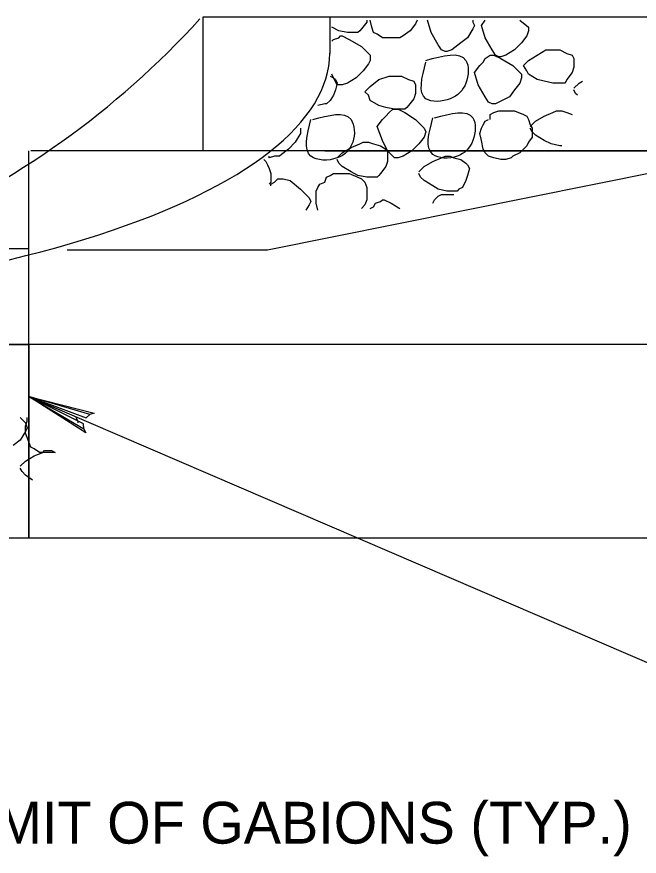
# Model space of a CAD drawing. Extents: x 593 to 1473, y 721 to 1315.
# Drawn here: x 853.8 to 898.5, y 813.2 to 873.4 of the extents above; entities that cross this region are included whole.
import ezdxf

# ---------------------------------------------------------------- set-up
doc = ezdxf.new("R2010")
doc.units = 0
doc.layers.add('1', color=7, linetype='Continuous')
doc.layers.add('2', color=7, linetype='Continuous')

msp = doc.modelspace()

# ---------------------------------------------------------------- linework, layer by layer
at = {"layer": '1'}
msp.add_lwpolyline([(858.655, 843.824), (858.63, 844.193), (854.709, 846.141), (858.655, 843.824), (858.79, 843.549), (854.709, 846.141), (858.807, 844.615), (859.082, 844.85), (854.709, 846.141), (859.394, 844.953), (859.082, 844.85)], dxfattribs=at)
msp.add_lwpolyline([(858.655, 843.824), (858.63, 844.193), (854.709, 846.141), (858.655, 843.824), (858.79, 843.549), (854.709, 846.141), (858.807, 844.615), (859.082, 844.85), (854.709, 846.141), (859.394, 844.953), (859.082, 844.85)], dxfattribs=at)
at = {"layer": '2'}
for p, q in [((876.334, 870.766), (876.334, 873.391)), ((932.209, 868.766), (871.834, 856.641)), ((861.959, 863.766), (854.834, 863.766)), ((871.459, 863.766), (861.959, 863.766)), ((872.584, 863.766), (871.459, 863.766)), ((876.334, 863.766), (872.584, 863.766)), ((819.834, 856.766), (854.709, 856.766)), ((871.834, 856.641), (857.459, 856.641)), ((854.709, 846.141), (925.949, 815.516)), ((854.709, 846.141), (925.949, 815.516))]:
    msp.add_line(p, q, dxfattribs=at)
for points in [[(867.209, 863.766), (867.209, 873.391), (876.084, 873.391)], [(876.084, 873.391), (932.209, 873.391), (932.209, 863.766), (871.459, 863.766)], [(876.959, 872.391), (876.459, 872.641)], [(876.459, 872.641), (876.459, 872.641)], [(878.959, 873.016), (878.584, 872.516)], [(878.959, 873.141), (878.959, 873.016)], [(879.334, 872.641), (879.209, 873.141)], [(879.459, 872.266), (879.334, 872.641)], [(882.459, 872.891), (882.084, 872.391)], [(882.584, 873.141), (882.459, 872.891)], [(883.584, 872.266), (883.334, 873.141)], [(886.584, 873.141), (886.584, 873.016)], [(886.584, 873.016), (886.709, 872.766)], [(886.709, 872.766), (886.584, 872.516)], [(887.209, 872.766), (887.459, 873.141)], [(887.459, 871.891), (887.209, 872.766)], [(889.959, 873.141), (890.584, 872.641)], [(890.584, 872.641), (890.584, 872.391)], [(877.584, 872.266), (876.959, 872.391)], [(876.959, 871.891), (877.084, 872.016)], [(877.084, 872.016), (877.209, 872.016)], [(877.209, 872.016), (877.709, 871.766)], [(878.334, 872.266), (877.584, 872.266)], [(878.459, 872.391), (878.334, 872.266)], [(878.584, 872.516), (878.459, 872.391)], [(879.709, 872.141), (879.459, 872.266)], [(880.084, 871.891), (879.709, 872.141)], [(881.584, 872.016), (881.334, 871.891)], [(882.084, 872.391), (881.584, 872.016)], [(884.084, 871.391), (883.584, 872.266)], [(886.584, 872.516), (886.209, 871.891)], [(890.459, 872.016), (890.084, 871.516)], [(890.584, 872.391), (890.459, 872.016)], [(876.459, 871.641), (876.584, 871.766)], [(876.584, 871.766), (876.959, 871.891)], [(877.709, 871.766), (878.584, 871.266)], [(880.584, 871.891), (880.084, 871.891)], [(880.959, 871.891), (880.584, 871.891)], [(881.334, 871.891), (880.959, 871.891)], [(885.709, 871.516), (885.084, 871.016)], [(886.209, 871.891), (885.709, 871.516)], [(887.959, 871.016), (887.459, 871.891)], [(890.084, 871.516), (889.584, 871.016)], [(878.584, 871.266), (879.209, 870.641)], [(884.334, 871.016), (884.084, 871.391)], [(884.584, 870.891), (884.334, 871.016)], [(884.709, 870.891), (884.584, 870.891)], [(885.084, 871.016), (884.709, 870.891)], [(888.209, 870.641), (887.959, 871.016)], [(889.584, 871.016), (888.959, 870.641)], [(891.209, 870.641), (891.834, 871.016)], [(891.834, 871.016), (892.084, 871.016)], [(892.084, 871.016), (892.459, 871.016)], [(892.459, 871.016), (892.834, 871.016)], [(892.834, 871.016), (893.334, 870.766)], [(879.209, 870.266), (879.084, 870.016)], [(879.209, 870.641), (879.209, 870.266)], [(887.334, 870.141), (887.459, 870.391)], [(887.459, 870.391), (887.834, 870.641)], [(887.834, 870.641), (887.959, 870.641)], [(887.959, 870.641), (888.084, 870.641)], [(888.084, 870.641), (888.584, 870.391)], [(888.459, 870.516), (888.209, 870.641)], [(888.584, 870.516), (888.459, 870.516)], [(888.959, 870.641), (888.584, 870.516)], [(888.584, 870.391), (889.459, 869.891)], [(890.209, 869.891), (890.584, 870.266)], [(890.584, 870.266), (891.209, 870.641)], [(893.334, 870.766), (893.709, 870.641)], [(893.709, 870.641), (893.834, 870.391)], [(893.834, 870.391), (893.834, 870.141)], [(879.084, 870.016), (878.709, 869.516)], [(886.709, 869.391), (887.084, 869.891)], [(887.084, 869.891), (887.334, 870.141)], [(889.459, 869.891), (890.084, 869.266)], [(890.459, 869.516), (890.209, 869.891)], [(893.834, 869.766), (893.709, 869.391)], [(893.834, 870.141), (893.834, 869.766)], [(876.334, 869.141), (876.584, 869.016)], [(876.584, 869.016), (876.459, 869.266)], [(876.834, 868.516), (876.584, 869.016)], [(876.584, 869.016), (876.709, 868.891)], [(878.209, 869.016), (877.584, 868.641)], [(878.709, 869.516), (878.209, 869.016)], [(879.834, 868.891), (880.584, 869.141)], [(880.584, 869.141), (880.709, 869.141)], [(880.709, 869.141), (881.209, 869.141)], [(881.209, 869.141), (881.459, 869.141)], [(881.459, 869.141), (881.959, 868.891)], [(886.959, 868.516), (886.709, 869.391)], [(890.084, 869.016), (889.959, 868.641)], [(890.084, 869.266), (890.084, 869.016)], [(890.584, 869.266), (890.459, 869.516)], [(891.209, 868.891), (890.584, 869.266)], [(893.709, 869.391), (893.334, 868.891)], [(876.709, 868.891), (876.834, 868.641)], [(876.834, 868.641), (876.709, 868.141)], [(877.084, 868.516), (876.834, 868.516)], [(877.209, 868.516), (877.084, 868.516)], [(877.584, 868.641), (877.209, 868.516)], [(879.209, 868.391), (879.834, 868.891)], [(881.959, 868.891), (882.334, 868.766)], [(882.334, 868.766), (882.459, 868.516)], [(882.459, 868.516), (882.459, 868.391)], [(887.459, 867.641), (886.959, 868.516)], [(889.959, 868.641), (889.584, 868.141)], [(891.709, 868.766), (891.209, 868.891)], [(892.334, 868.641), (891.709, 868.766)], [(893.084, 868.641), (892.334, 868.641)], [(893.209, 868.641), (893.084, 868.641)], [(893.334, 868.891), (893.209, 868.641)], [(893.834, 868.266), (894.209, 868.641)], [(894.209, 868.641), (894.459, 868.766)], [(876.709, 868.141), (876.584, 867.766)], [(878.834, 868.016), (879.209, 868.391)], [(879.084, 867.766), (878.834, 868.016)], [(882.459, 867.891), (882.334, 867.516)], [(882.459, 868.391), (882.459, 867.891)], [(889.584, 868.141), (889.209, 867.641)], [(893.959, 867.891), (893.834, 868.141)], [(894.084, 867.766), (893.959, 867.891)], [(876.334, 867.391), (876.084, 867.141)], [(876.584, 867.766), (876.334, 867.391)], [(879.209, 867.391), (879.084, 867.766)], [(879.834, 867.016), (879.209, 867.391)], [(882.334, 867.516), (881.959, 867.016)], [(887.709, 867.266), (887.459, 867.641)], [(887.959, 867.141), (887.709, 867.266)], [(888.459, 867.266), (888.209, 867.141)], [(889.209, 867.641), (888.459, 867.266)], [(875.959, 867.141), (875.459, 867.016)], [(876.084, 867.141), (875.959, 867.141)], [(880.334, 866.891), (879.834, 867.016)], [(880.959, 866.766), (880.334, 866.891)], [(880.584, 866.516), (880.834, 866.766)], [(880.834, 866.766), (880.959, 866.766)], [(880.959, 866.766), (881.209, 866.766)], [(881.709, 866.766), (880.959, 866.766)], [(881.209, 866.766), (881.709, 866.516)], [(881.834, 866.891), (881.709, 866.766)], [(881.959, 867.016), (881.834, 866.891)], [(888.209, 867.141), (887.959, 867.141)], [(888.084, 866.516), (888.459, 866.641)], [(888.459, 866.641), (889.084, 866.641)], [(889.084, 866.641), (889.584, 866.641)], [(889.584, 866.641), (890.209, 866.391)], [(892.334, 866.516), (892.584, 866.641)], [(892.584, 866.641), (892.959, 866.641)], [(892.959, 866.641), (893.334, 866.516)], [(879.709, 865.516), (880.084, 866.016)], [(880.084, 866.016), (880.334, 866.266)], [(880.334, 866.266), (880.584, 866.516)], [(881.709, 866.516), (882.459, 866.016)], [(882.459, 866.016), (883.084, 865.391)], [(887.459, 865.891), (887.709, 866.016)], [(887.834, 866.391), (888.084, 866.516)], [(887.834, 866.016), (887.834, 866.391)], [(890.209, 866.391), (890.459, 866.266)], [(890.459, 866.266), (890.584, 866.016)], [(890.584, 866.016), (890.709, 865.641)], [(891.084, 865.891), (891.709, 866.266)], [(891.709, 866.266), (892.334, 866.516)], [(893.334, 866.516), (893.709, 866.391)], [(874.209, 865.391), (874.209, 865.266)], [(880.084, 864.516), (879.709, 865.516)], [(883.084, 865.391), (883.209, 865.141)], [(887.084, 865.016), (887.209, 865.391)], [(887.209, 865.391), (887.334, 865.641)], [(887.334, 865.641), (887.459, 865.891)], [(890.709, 865.516), (891.084, 865.891)], [(890.709, 865.641), (890.834, 865.391)], [(890.834, 865.141), (890.709, 865.391)], [(890.834, 865.391), (890.834, 865.141)], [(874.209, 865.016), (873.959, 864.641)], [(874.209, 865.266), (874.209, 865.016)], [(883.209, 865.141), (883.084, 864.766)], [(887.209, 864.516), (887.084, 865.016)], [(890.834, 865.141), (890.834, 864.766)], [(891.084, 864.891), (890.834, 865.141)], [(891.709, 864.516), (891.084, 864.891)], [(873.834, 864.391), (873.334, 863.891)], [(873.959, 864.641), (873.834, 864.391)], [(877.834, 864.016), (878.459, 864.266)], [(878.459, 864.266), (878.709, 864.391)], [(878.709, 864.391), (879.084, 864.391)], [(879.084, 864.391), (879.459, 864.266)], [(879.459, 864.266), (879.959, 864.141)], [(880.459, 863.766), (880.084, 864.516)], [(882.709, 864.266), (882.209, 863.766)], [(883.084, 864.766), (882.709, 864.266)], [(887.334, 863.891), (887.209, 864.516)], [(890.584, 864.391), (890.459, 864.141)], [(890.834, 864.766), (890.584, 864.391)], [(892.209, 864.266), (891.709, 864.516)], [(892.834, 864.141), (892.209, 864.266)], [(875.959, 863.766), (932.209, 863.766), (932.209, 849.891), (854.709, 849.891), (854.709, 856.641)], [(854.709, 856.641), (854.709, 863.766)], [(871.459, 863.766), (867.209, 863.766)], [(873.334, 863.891), (872.834, 863.516)], [(876.834, 863.266), (877.209, 863.641)], [(877.209, 863.641), (877.834, 864.016)], [(879.959, 864.141), (880.334, 863.891)], [(880.334, 863.891), (880.459, 863.766)], [(880.834, 863.391), (880.459, 863.766)], [(880.459, 863.766), (880.459, 863.516)], [(882.209, 863.766), (881.584, 863.391)], [(887.459, 863.641), (887.334, 863.891)], [(887.709, 863.391), (887.459, 863.641)], [(889.959, 863.641), (889.459, 863.391)], [(890.459, 864.141), (889.959, 863.641)], [(892.959, 864.141), (892.834, 864.141)], [(871.584, 863.141), (871.709, 863.016)], [(871.709, 863.016), (871.834, 862.766)], [(872.334, 863.391), (871.959, 863.266)], [(871.959, 863.266), (871.959, 863.391)], [(872.709, 863.391), (872.334, 863.391)], [(872.834, 863.516), (872.709, 863.391)], [(876.959, 862.891), (876.834, 863.141)], [(880.459, 863.016), (880.334, 862.641)], [(880.459, 863.516), (880.459, 863.016)], [(880.959, 863.266), (880.834, 863.391)], [(881.209, 863.266), (880.959, 863.266)], [(881.584, 863.391), (881.209, 863.266)], [(883.084, 862.641), (883.709, 863.016)], [(883.709, 863.016), (884.334, 863.266)], [(884.334, 863.266), (884.584, 863.391)], [(884.584, 863.391), (884.959, 863.391)], [(884.959, 863.391), (885.209, 863.266)], [(885.209, 863.266), (885.709, 863.141)], [(885.709, 863.141), (886.084, 862.891)], [(888.084, 863.266), (887.709, 863.391)], [(888.584, 863.141), (888.084, 863.266)], [(888.959, 863.141), (888.584, 863.141)], [(889.334, 863.266), (888.959, 863.141)], [(889.459, 863.391), (889.334, 863.266)], [(871.834, 862.766), (871.959, 862.516)], [(871.959, 862.516), (872.084, 862.141)], [(877.209, 862.641), (876.959, 862.891)], [(877.834, 862.266), (877.209, 862.641)], [(880.334, 862.641), (879.959, 862.141)], [(882.709, 862.266), (883.084, 862.641)], [(886.084, 862.891), (886.209, 862.766)], [(886.209, 862.766), (886.334, 862.516)], [(886.334, 862.516), (886.209, 862.016)], [(872.084, 862.141), (872.084, 861.891)], [(872.084, 861.891), (872.084, 861.516)], [(875.959, 861.516), (876.084, 861.891)], [(876.084, 861.891), (876.334, 862.016)], [(876.334, 862.016), (876.584, 862.141)], [(876.584, 862.141), (877.209, 862.141)], [(877.209, 862.141), (877.709, 862.141)], [(877.709, 862.141), (878.334, 861.891)], [(878.334, 862.016), (877.834, 862.266)], [(878.959, 861.891), (878.334, 862.016)], [(878.334, 861.891), (878.584, 861.766)], [(879.709, 861.891), (878.959, 861.891)], [(879.834, 862.016), (879.709, 861.891)], [(879.959, 862.141), (879.834, 862.016)], [(882.834, 861.891), (882.709, 862.141)], [(883.084, 861.641), (882.834, 861.891)], [(886.209, 862.016), (886.084, 861.641)], [(872.084, 861.516), (871.959, 861.391)], [(872.084, 861.391), (872.334, 861.516)], [(872.084, 861.266), (872.084, 861.391)], [(872.334, 861.516), (872.584, 861.766)], [(872.584, 861.766), (872.709, 861.766)], [(872.709, 861.766), (872.959, 861.766)], [(872.959, 861.766), (873.459, 861.641)], [(873.459, 861.641), (874.209, 861.016)], [(875.459, 861.141), (875.584, 861.391)], [(875.584, 861.391), (875.959, 861.516)], [(878.584, 861.766), (878.834, 861.516)], [(878.834, 861.516), (878.959, 861.141)], [(883.709, 861.266), (883.084, 861.641)], [(884.084, 861.016), (883.709, 861.266)], [(886.084, 861.641), (885.834, 861.141)], [(874.209, 861.016), (874.834, 860.391)], [(875.334, 860.891), (875.459, 861.141)], [(875.334, 860.516), (875.334, 860.891)], [(878.959, 861.141), (878.959, 860.891)], [(878.959, 860.891), (878.959, 860.641)], [(878.959, 860.641), (878.959, 860.266)], [(884.709, 860.891), (884.084, 861.016)], [(884.084, 860.516), (884.334, 860.641)], [(884.334, 860.641), (884.959, 860.641)], [(885.459, 860.891), (884.709, 860.891)], [(884.959, 860.641), (885.209, 860.641)], [(885.584, 861.016), (885.459, 860.891)], [(885.834, 861.141), (885.584, 861.016)], [(874.834, 860.391), (874.959, 860.141)], [(874.959, 860.141), (874.834, 859.891)], [(875.334, 860.016), (875.334, 860.516)], [(875.459, 859.516), (875.334, 860.016)], [(878.959, 860.266), (878.834, 859.891)], [(879.459, 859.766), (879.584, 860.016)], [(879.584, 860.016), (879.959, 860.141)], [(879.959, 860.141), (880.084, 860.266)], [(880.084, 860.266), (880.209, 860.266)], [(880.209, 860.266), (880.709, 860.016)], [(880.709, 860.016), (881.334, 859.641)], [(883.709, 860.016), (883.834, 860.266)], [(883.834, 860.266), (884.084, 860.516)], [(874.834, 859.891), (874.584, 859.516)], [(878.834, 859.891), (878.584, 859.641)], [(878.584, 859.641), (878.584, 859.641)], [(879.209, 859.641), (879.459, 859.766)], [(819.834, 849.891), (854.709, 849.891), (854.709, 856.641)], [(819.834, 836.016), (854.709, 836.016), (854.709, 849.891), (819.834, 849.891)], [(854.084, 844.641), (854.459, 844.266)], [(854.459, 844.016), (854.584, 844.391)], [(854.584, 844.391), (854.584, 844.641)], [(854.584, 844.641), (854.584, 844.641)], [(858.084, 844.641), (858.209, 844.391)], [(858.209, 844.391), (858.209, 844.266)], [(854.459, 844.266), (854.584, 843.891)], [(854.459, 843.516), (854.459, 844.016)], [(854.584, 843.891), (854.459, 843.641)], [(854.459, 843.641), (854.084, 843.016)], [(854.709, 842.891), (854.459, 843.516)], [(854.084, 843.016), (853.584, 842.641)], [(854.834, 842.516), (854.709, 842.891)], [(855.084, 842.391), (854.834, 842.516)], [(855.459, 842.141), (855.084, 842.391)], [(855.084, 841.891), (855.709, 842.141)], [(855.959, 842.141), (855.459, 842.141)], [(855.709, 842.141), (855.834, 842.266)], [(855.834, 842.266), (856.334, 842.266)], [(856.209, 842.141), (855.959, 842.141)], [(856.584, 842.141), (856.209, 842.141)], [(856.334, 842.266), (856.584, 842.141)], [(854.084, 841.141), (854.459, 841.516)], [(854.459, 841.516), (855.084, 841.891)], [(854.209, 840.766), (854.084, 841.016)], [(854.459, 840.516), (854.209, 840.766)], [(854.959, 840.141), (854.459, 840.516)]]:
    msp.add_lwpolyline(points, dxfattribs=at)
msp.add_lwpolyline([(854.709, 849.891), (854.709, 836.016), (932.209, 836.016), (932.209, 849.891)], close=True, dxfattribs=at)
msp.add_arc((820.879, 915.207), 62.345, 269.07829, 317.69591, dxfattribs=at)
msp.add_ellipse((820.787, 870.773), major_axis=(55.514, 0), ratio=0.329084, start_param=4.695974, end_param=6.283185, dxfattribs=at)
for points in [[(883.209, 870.266), (886.084, 870.266), (886.084, 868.641), (884.959, 867.516), (883.209, 867.516), (883.209, 870.141)], [(875.084, 866.016), (877.834, 866.016), (877.959, 864.391), (876.834, 863.266), (874.959, 863.391), (874.959, 866.016)], [(883.834, 866.141), (886.584, 866.141), (886.584, 864.516), (885.459, 863.391), (883.709, 863.516), (883.709, 866.141)]]:
    msp.add_spline(points, degree=3, dxfattribs=at)

# ---------------------------------------------------------------- texts
msp.add_text('LIMIT OF GABIONS (TYP.)', height=3, dxfattribs=at).set_placement((848.957, 814.072))

doc.saveas('drawing.dxf')
